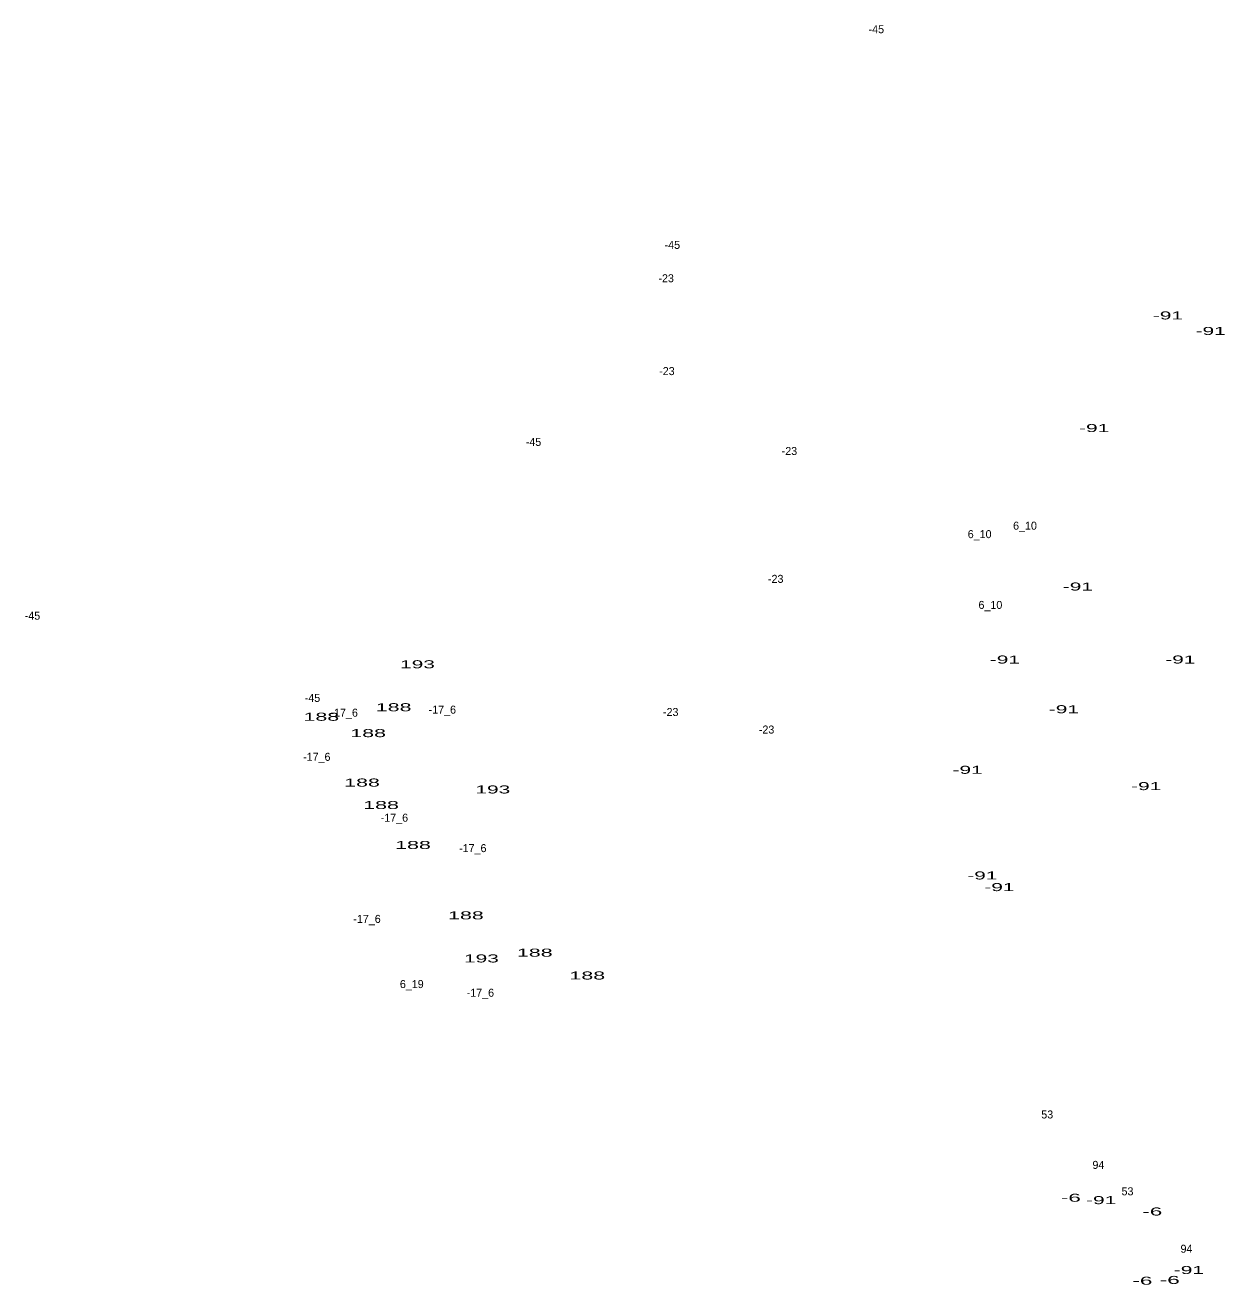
# Model space of a CAD drawing. Extents: x -659624 to -656248, y -1006345 to -1003555.
# Drawn here: x -657682 to -657087, y -1004222 to -1003592 of the extents above; entities that cross this region are included whole.
import ezdxf
from ezdxf.enums import TextEntityAlignment as Align

# ---------------------------------------------------------------- set-up
doc = ezdxf.new("R2010")
doc.units = 0
doc.header["$LTSCALE"] = 1.6
doc.layers.add('24', color=7, linetype='Continuous')

msp = doc.modelspace()

# ---------------------------------------------------------------- texts
at = {"layer": '24'}
for s, p in [('-45', (-657256.409, -1003596.46)), ('-45', (-657358.379, -1003704.29)), ('-23', (-657361.485, -1003720.98)), ('-23', (-657361.105, -1003767.4)), ('-45', (-657427.789, -1003802.81)), ('-23', (-657299.865, -1003807.35)), ('6_10', (-657204.768, -1003848.92)), ('6_10', (-657182.088, -1003844.69)), ('-23', (-657306.705, -1003871.28)), ('6_10', (-657199.388, -1003884.31)), ('-45', (-657678.269, -1003889.7)), ('-45', (-657538.289, -1003930.81)), ('-17_6', (-657473.367, -1003936.67)), ('-17_6', (-657522.427, -1003938.19)), ('-23', (-657359.195, -1003937.86)), ('-23', (-657311.275, -1003946.62)), ('-17_6', (-657536.127, -1003960.26)), ('-17_6', (-657497.327, -1003990.7)), ('-17_6', (-657458.147, -1004005.92)), ('-17_6', (-657511.017, -1004041.3)), ('6_19', (-657488.64, -1004073.87)), ('-17_6', (-657454.347, -1004078.21)), ('53', (-657170.977, -1004139.07)), ('94', (-657145.397, -1004164.27)), ('53', (-657130.857, -1004177.49)), ('94', (-657101.367, -1004206.2))]:
    msp.add_text(s, height=4, dxfattribs=at).set_placement(p, align=Align.CENTER)
for s, width, p in [('-91', 1.95, (-657110.645, -1003739.57)), ('-91', 1.95, (-657089.285, -1003747.34)), ('-91', 1.95, (-657147.525, -1003795.88)), ('-91', 1.95, (-657155.675, -1003875.11)), ('-91', 1.95, (-657192.155, -1003911.61)), ('-91', 1.95, (-657104.435, -1003911.61)), ('193', 1.95, (-657485.793, -1003913.98)), ('188', 2, (-657497.717, -1003935.46)), ('-91', 1.95, (-657162.655, -1003936.46)), ('188', 2, (-657533.857, -1003940.22)), ('188', 2, (-657510.457, -1003948.4)), ('-91', 1.95, (-657210.795, -1003966.75)), ('188', 2, (-657513.507, -1003973.13)), ('-91', 1.95, (-657121.505, -1003974.9)), ('193', 1.95, (-657448.133, -1003976.57)), ('188', 2, (-657503.997, -1003984.36)), ('188', 2, (-657488.027, -1004004.33)), ('-91', 1.95, (-657203.415, -1004019.57)), ('-91', 1.95, (-657194.885, -1004025.39)), ('188', 2, (-657461.577, -1004039.52)), ('193', 1.95, (-657453.833, -1004061.06)), ('188', 2, (-657427.157, -1004058.17)), ('188', 2, (-657400.907, -1004069.59)), ('-6', 2.1, (-657159.159, -1004180.7)), ('-91', 1.95, (-657144.025, -1004181.9)), ('-6', 2.1, (-657118.449, -1004187.58)), ('-91', 1.95, (-657100.165, -1004216.85)), ('-6', 2.1, (-657123.409, -1004222.18)), ('-6', 2.1, (-657109.719, -1004221.8))]:
    msp.add_text(s, height=4, dxfattribs=dict(at, width=width)).set_placement(p, align=Align.CENTER)

doc.saveas('drawing.dxf')
